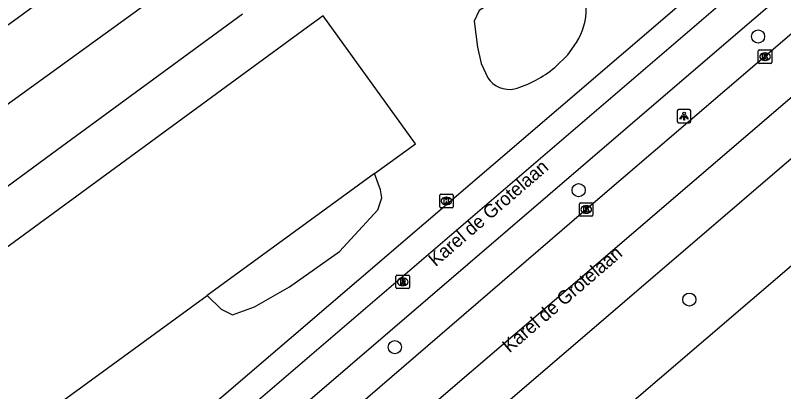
# Model space of a CAD drawing. Extents: x 159040 to 160094, y 381214 to 382518.
# Drawn here: x 159296.7 to 159353.9, y 381381.3 to 381409.3 of the extents above; entities that cross this region are included whole.
import ezdxf

# ---------------------------------------------------------------- set-up
doc = ezdxf.new("R2010")
doc.units = 0
for name, color, linetype in [('IMGEO_Boom', 7, 'Continuous'), ('IMGEO_Fietspad_gesloten', 7, 'Continuous'), ('IMGEO_Groenvoorziening', 7, 'Continuous'), ('IMGEO_Kolk', 7, 'Continuous'), ('IMGEO_Lichtpunt', 7, 'Continuous'), ('IMGEO_Openbare_ruimte_label', 7, 'Continuous'), ('IMGEO_Pand', 7, 'Continuous'), ('IMGEO_Parkeervlak_open', 7, 'Continuous'), ('IMGEO_Rijbaan_lokaal_halfverhard', 7, 'Continuous'), ('IMGEO_Rijbaan_regionaal_gesloten', 7, 'Continuous'), ('IMGEO_Rioolput', 7, 'Continuous'), ('IMGEO_Voetpad_open', 7, 'Continuous')]:
    doc.layers.add(name, color=color, linetype=linetype)

msp = doc.modelspace()

# ---------------------------------------------------------------- linework, layer by layer
at = {"layer": 'IMGEO_Boom'}
for centre in [(159352.037, 381407.724), (159338.659, 381396.267), (159346.911, 381388.113), (159324.954, 381384.566)]:
    msp.add_circle(centre, 0.489, dxfattribs=at)
at = {"layer": 'IMGEO_Fietspad_gesloten'}
for points in [[(159300.496, 381368.385), (159352.874, 381413.294), (159353.612, 381413.948), (159354.006, 381415.613), (159389.964, 381446.415)], [(159388.224, 381440.332), (159371.651, 381426.113), (159345.134, 381403.373), (159318.648, 381380.652), (159300.932, 381365.516), (159300.143, 381364.853), (159300.061, 381364.742)]]:
    msp.add_lwpolyline(points, dxfattribs=at)
at = {"layer": 'IMGEO_Groenvoorziening'}
for points in [[(159337.458, 381412.804), (159335.47, 381412.008), (159333.055, 381410.82), (159331.234, 381409.657), (159330.867, 381408.873), (159331.11, 381406.931), (159331.386, 381405.713), (159331.888, 381404.641)], [(159336.873, 381405.416), (159337.849, 381406.364), (159338.489, 381407.282)], [(159310.956, 381388.405), (159312, 381387.39), (159312.861, 381386.98), (159314.5, 381387.575), (159317.105, 381389.065), (159320.821, 381391.708), (159323.693, 381394.801), (159323.979, 381395.687), (159323.878, 381396.287), (159323.45, 381397.5)]]:
    msp.add_lwpolyline(points, dxfattribs=at)
for centre, radius, start, end in [((159334.668, 381409.763), 4.556, 327.0048, 35.3463), ((159331.613, 381411.688), 8.185, 285.9906, 309.9861), ((159333.482, 381405.684), 1.905, 213.202, 281.7063)]:
    msp.add_arc(centre, radius, start, end, dxfattribs=at)
at = {"layer": 'IMGEO_Kolk'}
for p, q in [((159352.054, 381405.794), (159352.054, 381406.646)), ((159352.129, 381406.72), (159352.981, 381406.72)), ((159353.055, 381406.646), (159353.055, 381405.794)), ((159352.542, 381406.5), (159352.567, 381406.5)), ((159352.981, 381405.72), (159352.129, 381405.72)), ((159352.565, 381405.94), (159352.54, 381405.94)), ((159328.302, 381395.036), (159328.302, 381395.888)), ((159328.377, 381395.962), (159329.229, 381395.962)), ((159328.79, 381395.742), (159328.815, 381395.742)), ((159329.303, 381395.888), (159329.303, 381395.036)), ((159328.813, 381395.182), (159328.788, 381395.182)), ((159338.723, 381394.405), (159338.723, 381395.257)), ((159338.798, 381395.331), (159339.65, 381395.331)), ((159339.724, 381395.257), (159339.724, 381394.405)), ((159329.229, 381394.962), (159328.377, 381394.962)), ((159339.211, 381395.111), (159339.236, 381395.111)), ((159339.65, 381394.331), (159338.798, 381394.331)), ((159339.234, 381394.551), (159339.209, 381394.551))]:
    msp.add_line(p, q, dxfattribs=at)
for points in [[(159352.054, 381405.794), (159352.054, 381406.646)], [(159352.129, 381406.72), (159352.981, 381406.72)], [(159353.055, 381406.646), (159353.055, 381405.794)], [(159352.375, 381406.42), (159352.498, 381406.42), (159352.498, 381406.269), (159352.628, 381406.42), (159352.792, 381406.42), (159352.646, 381406.269), (159352.799, 381406.02), (159352.647, 381406.02), (159352.562, 381406.184), (159352.498, 381406.117), (159352.498, 381406.02), (159352.375, 381406.02), (159352.375, 381406.42)], [(159352.981, 381405.72), (159352.129, 381405.72)], [(159328.302, 381395.036), (159328.302, 381395.888)], [(159328.377, 381395.962), (159329.229, 381395.962)], [(159329.303, 381395.888), (159329.303, 381395.036)], [(159328.623, 381395.662), (159328.746, 381395.662), (159328.746, 381395.511), (159328.876, 381395.662), (159329.04, 381395.662), (159328.894, 381395.511), (159329.047, 381395.262), (159328.895, 381395.262), (159328.81, 381395.426), (159328.746, 381395.359), (159328.746, 381395.262), (159328.623, 381395.262), (159328.623, 381395.662)], [(159338.723, 381394.405), (159338.723, 381395.257)], [(159338.798, 381395.331), (159339.65, 381395.331)], [(159339.724, 381395.257), (159339.724, 381394.405)], [(159329.229, 381394.962), (159328.377, 381394.962)], [(159339.044, 381395.031), (159339.167, 381395.031), (159339.167, 381394.88), (159339.297, 381395.031), (159339.461, 381395.031), (159339.315, 381394.88), (159339.468, 381394.631), (159339.316, 381394.631), (159339.231, 381394.795), (159339.167, 381394.728), (159339.167, 381394.631), (159339.044, 381394.631), (159339.044, 381395.031)], [(159339.65, 381394.331), (159338.798, 381394.331)]]:
    msp.add_lwpolyline(points, dxfattribs=at)
for centre, start, end in [((159352.131, 381406.644), 91.552, 178.448), ((159352.131, 381406.644), 91.552, 178.448), ((159352.979, 381406.644), 1.552, 88.448), ((159352.979, 381406.644), 1.552, 88.448), ((159352.131, 381405.796), 181.552, 268.448), ((159352.131, 381405.796), 181.552, 268.448), ((159352.979, 381405.796), 271.552, 358.448), ((159352.979, 381405.796), 271.552, 358.448), ((159328.379, 381395.886), 91.552, 178.448), ((159328.379, 381395.886), 91.552, 178.448), ((159329.227, 381395.886), 1.552, 88.448), ((159329.227, 381395.886), 1.552, 88.448), ((159338.8, 381395.255), 91.552, 178.448), ((159338.8, 381395.255), 91.552, 178.448), ((159339.648, 381395.255), 1.552, 88.448), ((159339.648, 381395.255), 1.552, 88.448), ((159328.379, 381395.038), 181.552, 268.448), ((159328.379, 381395.038), 181.552, 268.448), ((159329.227, 381395.038), 271.552, 358.448), ((159329.227, 381395.038), 271.552, 358.448), ((159338.8, 381394.407), 181.552, 268.448), ((159338.8, 381394.407), 181.552, 268.448), ((159339.648, 381394.407), 271.552, 358.448), ((159339.648, 381394.407), 271.552, 358.448)]:
    msp.add_arc(centre, 0.0765, start, end, dxfattribs=at)
for centre, major_axis, ratio, start_param, end_param in [((159352.541, 381406.22), (-0.387, 0.002), 0.722429, 4.712389, 7.853982), ((159352.566, 381406.22), (-0.39, 0.002), 0.717154, 1.570796, 4.712389), ((159328.789, 381395.462), (-0.387, 0.002), 0.722429, 4.712389, 7.853982), ((159328.814, 381395.462), (-0.39, 0.002), 0.717154, 1.570796, 4.712389), ((159339.21, 381394.831), (-0.387, 0.002), 0.722429, 4.712389, 7.853982), ((159339.235, 381394.831), (-0.39, 0.002), 0.717154, 1.570796, 4.712389)]:
    msp.add_ellipse(centre, major_axis=major_axis, ratio=ratio, start_param=start_param, end_param=end_param, dxfattribs=at)
at = {"layer": 'IMGEO_Lichtpunt'}
for p, q in [((159346.015, 381402.183), (159346.015, 381401.376)), ((159346.015, 381402.183), (159346.015, 381401.376)), ((159346.917, 381402.278), (159346.109, 381402.278)), ((159346.917, 381402.278), (159346.109, 381402.278)), ((159347.011, 381401.376), (159347.011, 381402.183)), ((159347.011, 381401.376), (159347.011, 381402.183)), ((159346.109, 381401.282), (159346.917, 381401.282)), ((159346.109, 381401.282), (159346.917, 381401.282))]:
    msp.add_line(p, q, dxfattribs=at)
for points in [[(159346.389, 381401.847), (159346.428, 381401.819), (159346.24, 381401.557), (159346.202, 381401.584), (159346.389, 381401.847)], [(159346.491, 381401.799), (159346.538, 381401.799), (159346.538, 381401.477), (159346.491, 381401.477), (159346.491, 381401.799)], [(159346.601, 381401.819), (159346.639, 381401.846), (159346.826, 381401.584), (159346.787, 381401.556), (159346.601, 381401.819)]]:
    msp.add_lwpolyline(points, dxfattribs=at)
msp.add_circle((159346.514, 381401.981), 0.0994, dxfattribs=at)
for centre, start, end in [((159346.109, 381402.183), 90, 180), ((159346.109, 381402.183), 90, 180), ((159346.917, 381402.183), 0, 90), ((159346.917, 381402.183), 0, 90), ((159346.109, 381401.376), 180, 270), ((159346.109, 381401.376), 180, 270), ((159346.917, 381401.376), 270, 0), ((159346.917, 381401.376), 270, 360)]:
    msp.add_arc(centre, 0.0946, start, end, dxfattribs=at)
at = {"layer": 'IMGEO_Pand'}
for points in [[(159323.45, 381397.5), (159326.496, 381399.717), (159319.619, 381409.269), (159318.449, 381408.412), (159290.547, 381387.99), (159289.626, 381389.249), (159286.22, 381393.893), (159281.63, 381390.527), (159281.722, 381390.399), (159289.861, 381379.251), (159291.687, 381380.535), (159294.623, 381376.516), (159310.956, 381388.405)], [(159323.45, 381397.5), (159310.956, 381388.405)]]:
    msp.add_lwpolyline(points, dxfattribs=at)
at = {"layer": 'IMGEO_Parkeervlak_open'}
msp.add_lwpolyline([(159286.146, 381395.501), (159289.128, 381391.46), (159298.99, 381398.693), (159313.605, 381409.412)], dxfattribs=at)
at = {"layer": 'IMGEO_Rijbaan_lokaal_halfverhard'}
for points in [[(159277.551, 381395.074), (159315.041, 381422.408), (159315.506, 381421.872), (159317.581, 381419.482), (159318.2, 381418.731)], [(159286.146, 381395.501), (159310.736, 381413.322)]]:
    msp.add_lwpolyline(points, dxfattribs=at)
at = {"layer": 'IMGEO_Rijbaan_regionaal_gesloten'}
for points in [[(159524.392, 381565.298), (159524.318, 381565.22), (159513.487, 381553.459), (159509.914, 381549.667), (159499.797, 381539.047), (159492.644, 381531.758), (159482.267, 381521.51), (159465.201, 381505.256), (159442.492, 381484.426), (159434.773, 381477.467), (159414.042, 381459.154), (159404.558, 381450.901), (159395.563, 381443.073), (159354.89, 381408.246), (159339.224, 381394.831), (159304.87, 381365.271), (159301.884, 381362.731)], [(159223.955, 381291.092), (159228.218, 381294.768), (159249.8, 381313.294), (159261.119, 381323.01), (159270.676, 381331.27), (159281.84, 381340.822), (159296.948, 381353.793), (159309.361, 381364.454), (159324.607, 381377.572), (159336.854, 381388.065), (159355.279, 381403.848), (159370.545, 381416.887), (159383.498, 381428.039), (159401.924, 381443.755), (159413.428, 381453.788), (159429.207, 381467.675), (159453.123, 381489.287), (159476.095, 381510.615), (159487.725, 381521.828), (159499.136, 381533.249), (159515.536, 381550.447), (159526.975, 381562.783)], [(159306.514, 381357.491), (159404.195, 381441.263), (159409.309, 381445.71), (159416.317, 381451.803), (159432.909, 381466.414), (159448.426, 381480.359), (159461.511, 381492.336), (159474.06, 381504.012), (159488.86, 381518.149), (159495.714, 381524.98), (159529.443, 381560.38)], [(159536.368, 381553.774), (159525.014, 381542.388), (159507.251, 381525.399), (159490.066, 381509.393), (159472.78, 381493.666), (159455.885, 381478.555), (159436.893, 381461.755), (159418.54, 381445.713), (159413.374, 381441.268), (159355.053, 381391.082), (159310.488, 381352.927)]]:
    msp.add_lwpolyline(points, dxfattribs=at)
at = {"layer": 'IMGEO_Rioolput'}
for p, q in [((159325.041, 381389.007), (159325.041, 381389.859)), ((159325.116, 381389.933), (159325.968, 381389.933)), ((159325.529, 381389.713), (159325.554, 381389.713)), ((159326.042, 381389.859), (159326.042, 381389.007)), ((159325.968, 381388.933), (159325.116, 381388.933)), ((159325.552, 381389.153), (159325.527, 381389.153))]:
    msp.add_line(p, q, dxfattribs=at)
for points in [[(159325.041, 381389.007), (159325.041, 381389.859)], [(159325.116, 381389.933), (159325.968, 381389.933)], [(159325.63, 381389.631), (159325.378, 381389.633), (159325.378, 381389.233)], [(159325.556, 381389.552), (159325.502, 381389.552), (159325.502, 381389.471)], [(159325.502, 381389.471), (159325.554, 381389.471)], [(159326.042, 381389.859), (159326.042, 381389.007)], [(159325.968, 381388.933), (159325.116, 381388.933)], [(159325.378, 381389.233), (159325.502, 381389.233), (159325.502, 381389.395), (159325.513, 381389.395)], [(159325.56, 381389.366), (159325.631, 381389.233), (159325.771, 381389.233), (159325.706, 381389.359)]]:
    msp.add_lwpolyline(points, dxfattribs=at)
for centre, radius, start, end in [((159325.118, 381389.857), 0.0765, 91.552, 178.448), ((159325.118, 381389.857), 0.0765, 91.552, 178.448), ((159325.538, 381389.66), 0.19, 274.7715, 282.9687), ((159325.562, 381389.456), 0.0964, 77.0061, 93.1865), ((159325.576, 381389.513), 0.0378, 276.6634, 79.6772), ((159325.629, 381389.521), 0.109, 350.3612, 89.416), ((159325.627, 381389.521), 0.112, 277.5842, 350.9817), ((159325.966, 381389.857), 0.0765, 1.552, 88.448), ((159325.966, 381389.857), 0.0765, 1.552, 88.448), ((159325.118, 381389.009), 0.0765, 181.552, 268.448), ((159325.118, 381389.009), 0.0765, 181.552, 268.448), ((159325.512, 381389.342), 0.0533, 26.0293, 88.6989), ((159325.611, 381389.306), 0.108, 29.5134, 73.7905), ((159325.966, 381389.009), 0.0765, 271.552, 358.448), ((159325.966, 381389.009), 0.0765, 271.552, 358.448)]:
    msp.add_arc(centre, radius, start, end, dxfattribs=at)
for centre, major_axis, ratio, start_param, end_param in [((159325.528, 381389.433), (-0.387, 0.002), 0.722429, 4.712389, 7.853982), ((159325.553, 381389.433), (-0.39, 0.002), 0.717154, 1.570796, 4.712389)]:
    msp.add_ellipse(centre, major_axis=major_axis, ratio=ratio, start_param=start_param, end_param=end_param, dxfattribs=at)
at = {"layer": 'IMGEO_Voetpad_open'}
msp.add_lwpolyline([(159352.036, 381415.106), (159297.175, 381368.084)], dxfattribs=at)

# ---------------------------------------------------------------- texts
at = {"layer": 'IMGEO_Openbare_ruimte_label'}
for p in [(159327.993, 381390.524), (159333.502, 381384.097)]:
    msp.add_text('Karel de Grotelaan', height=1, rotation=40.7816, dxfattribs=at).set_placement(p)

doc.saveas('drawing.dxf')
